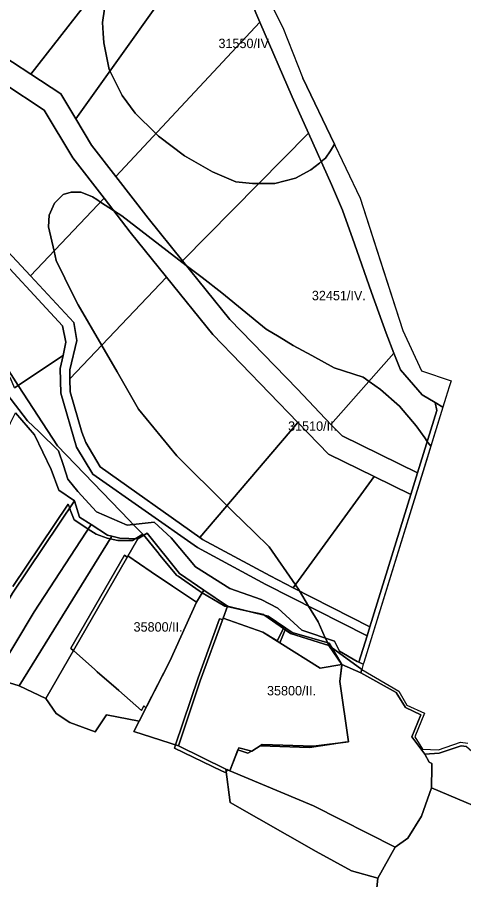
# Model space of a CAD drawing. Extents: x -522079 to -518833, y -1142400 to -1139961.
# Drawn here: x -519685.2 to -519448.3, y -1141371.1 to -1140913.1 of the extents above; entities that cross this region are included whole.
import ezdxf

# ---------------------------------------------------------------- set-up
doc = ezdxf.new("R2010")
doc.units = 0
for name, color, linetype in [('95560013', 7, 'Continuous'), ('95590013', 7, 'Continuous'), ('95610013', 7, 'Continuous'), ('95620013', 7, 'Continuous'), ('95630013', 7, 'Continuous'), ('95640013', 7, 'Continuous'), ('95660013', 7, 'Continuous')]:
    doc.layers.add(name, color=color, linetype=linetype)

msp = doc.modelspace()

# ---------------------------------------------------------------- linework, layer by layer
at = {"layer": '95560013'}
for points in [[(-519758.42, -1140883.91), (-519698.98, -1140816.54), (-519677.02, -1140829.78), (-519655.55, -1140840.89), (-519633.63, -1140850.83), (-519613.39, -1140860.38), (-519678.04, -1140943.34), (-519697.68, -1140930.5)], [(-519654.13, -1140967.02), (-519587.52, -1140873.31), (-519580.34, -1140878), (-519573.15, -1140884.93), (-519566.48, -1140893.71), (-519561.03, -1140904.86), (-519556.41, -1140915.6), (-519632.87, -1140997.67), (-519645.74, -1140981.03)], [(-519530.67, -1140974.63), (-519597.55, -1141042.38), (-519615.79, -1141019.75), (-519632.87, -1140997.67), (-519556.41, -1140915.6), (-519539.28, -1140955.41)], [(-519692.38, -1140948.3), (-519670.91, -1140962.34), (-519655.67, -1140987.81), (-519639.1, -1141009.23), (-519678.16, -1141050.41), (-519704.97, -1141021.67), (-519737.76, -1141001.71), (-519738.84, -1141001.14)], [(-519597.55, -1141042.38), (-519530.67, -1140974.63), (-519518.48, -1141001.84), (-519512.69, -1141015.45), (-519506.32, -1141033.4), (-519497.19, -1141059.15), (-519489.53, -1141080.75), (-519485.33, -1141091.52), (-519518.89, -1141129.28), (-519536.59, -1141110.65), (-519572.39, -1141073.59)], [(-519678.16, -1141050.41), (-519639.1, -1141009.23), (-519625.22, -1141027.17), (-519605.96, -1141051.06), (-519657.23, -1141105.11), (-519657.33, -1141100.32), (-519653.67, -1141084.78), (-519655.12, -1141075.09)], [(-519605.96, -1141051.06), (-519581.39, -1141081.54), (-519536.28, -1141128.25), (-519588.4, -1141189.29), (-519641.2, -1141151.84), (-519648.88, -1141138.93), (-519650.97, -1141133.45), (-519657.08, -1141111.95), (-519657.23, -1141105.11)], [(-519462.56, -1141121.92), (-519472.79, -1141154.97), (-519512.81, -1141135.27), (-519518.89, -1141129.28), (-519485.33, -1141091.52), (-519481.95, -1141100.21), (-519470.4, -1141113.6), (-519463.51, -1141117.64)], [(-519588.4, -1141189.29), (-519536.28, -1141128.25), (-519519.99, -1141145.11), (-519495.79, -1141157.02), (-519538.78, -1141215.99), (-519550.99, -1141209.75), (-519586.93, -1141190.33)], [(-519476.38, -1141166.58), (-519498.1, -1141236.79), (-519538.78, -1141215.99), (-519495.79, -1141157.02)]]:
    msp.add_lwpolyline(points, close=True, dxfattribs=at)
at = {"layer": '95590013'}
msp.add_lwpolyline([(-519702.3, -1141032.7), (-519661.22, -1141076.98), (-519659.49, -1141085.69), (-519660.92, -1141092.62), (-519686.59, -1141109.94), (-519688.8, -1141104.67), (-519698.11, -1141093.5), (-519702.87, -1141087.27), (-519704.67, -1141084.75), (-519705.02, -1141083.87), (-519715.52, -1141069.7), (-519725.48, -1141067.48)], close=True, dxfattribs=at)
at = {"layer": '95610013'}
for points in [[(-519587.52, -1140873.31), (-519654.13, -1140967.02), (-519662.03, -1140953.81), (-519678.04, -1140943.34), (-519613.39, -1140860.38), (-519591.11, -1140871.05)], [(-519555.19, -1141299.24), (-519560.68, -1141302.79), (-519567.64, -1141300.94), (-519572.4, -1141313.2), (-519574.58, -1141312.28), (-519599.57, -1141299.96), (-519588.13, -1141265.46), (-519575.99, -1141232.08), (-519554.92, -1141239.55), (-519545.8, -1141245.26), (-519524.47, -1141258.63), (-519512.96, -1141256.69), (-519514.13, -1141265.79), (-519509.48, -1141297.81), (-519527.97, -1141300.15)]]:
    msp.add_lwpolyline(points, close=True, dxfattribs=at)
at = {"layer": '95620013'}
for points in [[(-519687.67, -1141218.86), (-519709.65, -1141256.63), (-519720.8, -1141249.93), (-519714.2, -1141233.06), (-519705.26, -1141212.3), (-519728.23, -1141211.06), (-519688.75, -1141128.51), (-519686.19, -1141123.12), (-519676.06, -1141134.77), (-519667.13, -1141153.28), (-519663.19, -1141164.28), (-519654.81, -1141169.94)], [(-519697.46, -1141263.95), (-519709.65, -1141256.63), (-519687.67, -1141218.86), (-519654.81, -1141169.94), (-519652.19, -1141178.57), (-519646.01, -1141182.51), (-519676.14, -1141228.74)], [(-519635, -1141188.59), (-519684.2, -1141268.01), (-519697.46, -1141263.95), (-519676.14, -1141228.74), (-519646.01, -1141182.51), (-519637.37, -1141188.02)], [(-519670.06, -1141274.78), (-519621.3, -1141190.09), (-519616.23, -1141186.99), (-519599.05, -1141208.49), (-519586.25, -1141217.21), (-519590.16, -1141223.69), (-519604.3, -1141255.01), (-519620.55, -1141286.87), (-519637.83, -1141283.43), (-519643.91, -1141292.54), (-519657.26, -1141287.51), (-519664.55, -1141282.82)], [(-519684.2, -1141268.01), (-519635, -1141188.59), (-519630.7, -1141189.62), (-519621.3, -1141190.09), (-519670.06, -1141274.78)], [(-519620.55, -1141286.87), (-519604.3, -1141255.01), (-519590.16, -1141223.69), (-519586.25, -1141217.21), (-519573.7, -1141225.77), (-519575.99, -1141232.08), (-519588.13, -1141265.46), (-519599.57, -1141299.96), (-519623.35, -1141292.36)], [(-519554.92, -1141239.55), (-519575.99, -1141232.08), (-519573.7, -1141225.77), (-519552.03, -1141231.12), (-519542.77, -1141237.45), (-519545.8, -1141245.26)], [(-519470.8, -1141337.38), (-519477.91, -1141348.96), (-519484.66, -1141353.81), (-519528.06, -1141331.89), (-519572.4, -1141313.2), (-519567.64, -1141300.94), (-519560.68, -1141302.79), (-519555.19, -1141299.24), (-519527.97, -1141300.15), (-519509.48, -1141297.81), (-519514.13, -1141265.79), (-519512.96, -1141256.69), (-519502.94, -1141261.24), (-519484.08, -1141271.62), (-519479.21, -1141279.64), (-519471.1, -1141283.41), (-519475.87, -1141295.24), (-519468.94, -1141304.33), (-519466.74, -1141308.54), (-519465.25, -1141309.34), (-519465.26, -1141311.18), (-519465.42, -1141322.27)], [(-519385.2, -1141356.16), (-519465.42, -1141322.27), (-519465.26, -1141311.18), (-519465.25, -1141309.34), (-519466.74, -1141308.54), (-519468.94, -1141304.33), (-519461.31, -1141303.85), (-519449.71, -1141299.98), (-519446.9, -1141300.29), (-519442.41, -1141304.27), (-519431.85, -1141306.14), (-519427.38, -1141312.36), (-519420.99, -1141316.12), (-519419.15, -1141315.48), (-519371.28, -1141333.68)], [(-519528.06, -1141331.89), (-519484.66, -1141353.81), (-519493.9, -1141370.24), (-519507.9, -1141366.28), (-519526.67, -1141356.01), (-519572.25, -1141330.06), (-519574.58, -1141312.28), (-519572.4, -1141313.2)], [(-519494.92, -1141380.6), (-519493.9, -1141370.24), (-519484.66, -1141353.81), (-519477.91, -1141348.96), (-519470.8, -1141337.38), (-519465.42, -1141322.27), (-519385.2, -1141356.16), (-519392.16, -1141399.31), (-519386.73, -1141417.35), (-519402.53, -1141416.1), (-519450.75, -1141420.94), (-519466.91, -1141416.21), (-519490.7, -1141404.57), (-519496.45, -1141402.69), (-519489.99, -1141393.96), (-519488.36, -1141388.76)]]:
    msp.add_lwpolyline(points, close=True, dxfattribs=at)
msp.add_lwpolyline([(-519697.46, -1141263.95), (-519684.2, -1141268.01), (-519670.06, -1141274.78), (-519664.55, -1141282.82), (-519657.26, -1141287.51), (-519643.91, -1141292.54), (-519637.83, -1141283.43), (-519620.55, -1141286.87), (-519623.35, -1141292.36), (-519599.57, -1141299.96), (-519574.58, -1141312.28), (-519572.25, -1141330.06), (-519526.67, -1141356.01), (-519507.9, -1141366.28), (-519493.9, -1141370.24), (-519494.92, -1141380.6)], dxfattribs=at)
at = {"layer": '95630013'}
for points in [[(-519690.7, -1141113), (-519679.71, -1141127.39), (-519673.55, -1141133.3), (-519663.4, -1141143.35), (-519660.65, -1141151.03), (-519658.41, -1141158.35), (-519653.03, -1141164.92), (-519643.13, -1141175.65), (-519626.9, -1141182.72), (-519612.48, -1141181.23), (-519603.54, -1141189.56), (-519590.58, -1141204.82), (-519572.33, -1141216.46), (-519555.86, -1141222.18), (-519546.94, -1141226.78), (-519534.2, -1141238.58), (-519516.96, -1141244.4), (-519514.28, -1141249.74), (-519504.82, -1141255.11), (-519503.9, -1141255.56), (-519501.64, -1141256.67), (-519502.46, -1141259.44), (-519502.94, -1141261.24), (-519512.96, -1141256.69), (-519519.64, -1141245.38), (-519539.27, -1141239.84), (-519542.77, -1141237.45), (-519552.03, -1141231.12), (-519573.7, -1141225.77), (-519586.25, -1141217.21), (-519599.05, -1141208.49), (-519616.23, -1141186.99), (-519621.3, -1141190.09), (-519630.7, -1141189.62), (-519635, -1141188.59), (-519637.37, -1141188.02), (-519646.01, -1141182.51), (-519652.19, -1141178.57), (-519654.81, -1141169.94), (-519663.19, -1141164.28), (-519667.13, -1141153.28), (-519676.06, -1141134.77), (-519686.19, -1141123.12)], [(-519446.9, -1141300.29), (-519449.71, -1141299.98), (-519461.31, -1141303.85), (-519468.94, -1141304.33), (-519475.87, -1141295.24), (-519471.1, -1141283.41), (-519479.21, -1141279.64), (-519484.08, -1141271.62), (-519502.94, -1141261.24), (-519502.46, -1141259.44), (-519482.78, -1141270.88), (-519478.58, -1141278.28), (-519469.18, -1141282.65), (-519474.2, -1141295.1), (-519470.14, -1141301.74), (-519461.74, -1141302), (-519449.98, -1141298.09), (-519446.22, -1141298.48)]]:
    msp.add_lwpolyline(points, dxfattribs=at)
msp.add_lwpolyline([(-519462.56, -1141121.92), (-519463.51, -1141117.64), (-519459.37, -1141120.07), (-519501.33, -1141255.67), (-519501.64, -1141256.67), (-519503.9, -1141255.56), (-519499.59, -1141241.58), (-519498.1, -1141236.79), (-519476.38, -1141166.58), (-519472.79, -1141154.97)], close=True, dxfattribs=at)
at = {"layer": '95640013'}
for points in [[(-519569.14, -1140869.38), (-519544.31, -1140918.54), (-519533.66, -1140945.39), (-519503.31, -1141009.21), (-519480.71, -1141079.48), (-519470.66, -1141100.87), (-519455.06, -1141106.14), (-519456.05, -1141109.33), (-519457.77, -1141114.91), (-519459.37, -1141120.07), (-519463.51, -1141117.64), (-519470.4, -1141113.6), (-519481.95, -1141100.21), (-519485.33, -1141091.52), (-519489.53, -1141080.75), (-519497.19, -1141059.15), (-519506.32, -1141033.4), (-519512.69, -1141015.45), (-519518.48, -1141001.84), (-519530.67, -1140974.63), (-519539.28, -1140955.41), (-519556.41, -1140915.6), (-519561.03, -1140904.86)], [(-519697.68, -1140930.5), (-519678.04, -1140943.34), (-519662.03, -1140953.81), (-519654.13, -1140967.02), (-519645.74, -1140981.03), (-519632.87, -1140997.67), (-519615.79, -1141019.75), (-519597.55, -1141042.38), (-519572.39, -1141073.59), (-519536.59, -1141110.65), (-519518.89, -1141129.28), (-519512.81, -1141135.27), (-519472.79, -1141154.97), (-519476.38, -1141166.58), (-519495.79, -1141157.02), (-519519.99, -1141145.11), (-519536.28, -1141128.25), (-519581.39, -1141081.54), (-519605.96, -1141051.06), (-519625.22, -1141027.17), (-519639.1, -1141009.23), (-519655.67, -1140987.81), (-519670.91, -1140962.34), (-519692.38, -1140948.3)], [(-519704.97, -1141021.67), (-519678.16, -1141050.41), (-519655.12, -1141075.09), (-519653.67, -1141084.78), (-519657.33, -1141100.32), (-519657.23, -1141105.11), (-519657.08, -1141111.95), (-519650.97, -1141133.45), (-519648.88, -1141138.93), (-519641.2, -1141151.84), (-519588.4, -1141189.29), (-519586.93, -1141190.33), (-519550.99, -1141209.75), (-519538.78, -1141215.99), (-519498.1, -1141236.79), (-519499.59, -1141241.58), (-519553.27, -1141214.2), (-519589.6, -1141194.6), (-519645.14, -1141155.67), (-519653.82, -1141141.35), (-519662.06, -1141112.71), (-519662.35, -1141099.54), (-519660.92, -1141092.62), (-519659.49, -1141085.69), (-519661.22, -1141076.98), (-519702.3, -1141032.7)], [(-519686.59, -1141109.94), (-519660.92, -1141092.62), (-519662.35, -1141099.54), (-519662.06, -1141112.71), (-519653.82, -1141141.35), (-519645.14, -1141155.67), (-519589.6, -1141194.6), (-519553.27, -1141214.2), (-519499.59, -1141241.58), (-519503.9, -1141255.56), (-519504.82, -1141255.11), (-519514.28, -1141249.74), (-519516.96, -1141244.4), (-519534.2, -1141238.58), (-519546.94, -1141226.78), (-519555.86, -1141222.18), (-519572.33, -1141216.46), (-519590.58, -1141204.82), (-519603.54, -1141189.56), (-519612.48, -1141181.23), (-519626.9, -1141182.72), (-519643.13, -1141175.65), (-519653.03, -1141164.92), (-519658.41, -1141158.35), (-519660.65, -1141151.03), (-519663.4, -1141143.35), (-519673.55, -1141133.3), (-519679.71, -1141127.39), (-519690.7, -1141113)]]:
    msp.add_lwpolyline(points, dxfattribs=at)
msp.add_lwpolyline([(-519524.47, -1141258.63), (-519545.8, -1141245.26), (-519542.77, -1141237.45), (-519539.27, -1141239.84), (-519519.64, -1141245.38), (-519512.96, -1141256.69)], close=True, dxfattribs=at)
at = {"layer": '95660013'}
for points in [[(-519569.14, -1140869.38), (-519544.31, -1140918.54), (-519533.66, -1140945.39), (-519516.96, -1140980.51), (-519518.95, -1140984.06), (-519521.57, -1140987.86), (-519523.9, -1140989.74), (-519524.88, -1140990.52), (-519529.4, -1140994.15), (-519537.54, -1140998.54), (-519548.5, -1141001.37), (-519557.07, -1141001.37), (-519560.4, -1141001.37), (-519569.16, -1141000.43), (-519581.69, -1140995.09), (-519596.41, -1140986.61), (-519610.19, -1140976.25), (-519611.61, -1140974.85), (-519622.71, -1140964), (-519629.6, -1140954.57), (-519636.06, -1140941.6), (-519636.49, -1140940.75), (-519639.31, -1140926.61), (-519639.6, -1140921.53), (-519639.93, -1140915.93), (-519638.05, -1140902.43)], [(-519638.05, -1140902.43), (-519639.93, -1140915.93), (-519639.6, -1140921.53), (-519639.31, -1140926.61), (-519636.49, -1140940.75), (-519636.06, -1140941.6), (-519629.6, -1140954.57), (-519622.71, -1140964), (-519611.61, -1140974.85), (-519610.19, -1140976.25), (-519596.41, -1140986.61), (-519581.69, -1140995.09), (-519569.16, -1141000.43), (-519560.4, -1141001.37), (-519557.07, -1141001.37), (-519548.5, -1141001.37), (-519537.54, -1140998.54), (-519529.4, -1140994.15), (-519524.88, -1140990.52), (-519523.9, -1140989.74), (-519521.57, -1140987.86), (-519518.95, -1140984.06), (-519516.96, -1140980.51), (-519533.66, -1140945.39), (-519503.31, -1141009.21), (-519492.53, -1141042.73), (-519480.71, -1141079.48), (-519470.66, -1141100.87), (-519455.06, -1141106.14), (-519456.05, -1141109.33), (-519457.77, -1141114.91), (-519459.37, -1141120.07), (-519465.79, -1141140.81), (-519467.15, -1141139), (-519467.63, -1141138.31), (-519468.94, -1141136.48), (-519473.54, -1141130.01), (-519482.42, -1141119.57), (-519492.53, -1141110.66), (-519498.57, -1141106.42), (-519501.71, -1141104.21), (-519517.02, -1141099.29), (-519528.96, -1141092.71), (-519538.76, -1141087.32), (-519546.31, -1141082.8), (-519553.15, -1141078.71), (-519576.72, -1141059.36), (-519587.13, -1141051.34), (-519595.58, -1141044.83), (-519629.69, -1141018.52), (-519634.16, -1141015.62), (-519640.97, -1141011.2), (-519643.01, -1141009.87), (-519645.3, -1141008.38), (-519649.09, -1141006.86), (-519651.43, -1141005.93), (-519656.63, -1141005.93), (-519660.92, -1141007.16), (-519665.51, -1141011.76), (-519668.27, -1141018.21), (-519668.57, -1141024.35), (-519665.69, -1141037.26), (-519664.59, -1141042.17), (-519655.31, -1141061.04), (-519652.96, -1141065.82), (-519640.38, -1141087.34), (-519632.14, -1141101.44), (-519620.81, -1141121.1), (-519600.6, -1141145.98), (-519573.98, -1141172.41), (-519570.9, -1141175.46), (-519559.55, -1141186.49), (-519551.62, -1141194.2), (-519537.64, -1141214.42), (-519535.7, -1141217.23), (-519535.41, -1141217.71), (-519530.59, -1141225.77), (-519525.59, -1141234.12), (-519521.78, -1141242.52), (-519521.65, -1141242.82), (-519520.61, -1141245.1), (-519520.44, -1141245.48), (-519519.93, -1141246.59), (-519540.28, -1141240.34), (-519543.11, -1141238.33), (-519543.97, -1141237.72), (-519553.9, -1141230.66), (-519554.03, -1141230.56), (-519554.4, -1141230.29), (-519563.68, -1141228.24), (-519573.78, -1141226), (-519575.01, -1141225.73), (-519587.11, -1141218.63), (-519588.75, -1141217.67), (-519599.88, -1141209.94), (-519600.53, -1141209.49), (-519609.5, -1141198.7), (-519609.98, -1141198.13), (-519610.5, -1141197.51), (-519618.13, -1141188.15), (-519618.57, -1141187.61), (-519623.62, -1141182.38), (-519625.86, -1141180.06), (-519663.82, -1141140.73), (-519684.63, -1141108.61), (-519698.14, -1141087.76)], [(-519698.14, -1141087.76), (-519684.63, -1141108.61), (-519663.82, -1141140.73), (-519625.86, -1141180.06), (-519623.62, -1141182.38), (-519618.57, -1141187.61), (-519622.57, -1141190.02), (-519623.97, -1141190.87), (-519631.88, -1141190.86), (-519635.9, -1141190.04), (-519637.58, -1141189.69), (-519643.39, -1141187.64), (-519647.55, -1141184.87), (-519648.76, -1141184.06), (-519654.98, -1141179.93), (-519657.04, -1141174.68), (-519657.39, -1141173.78), (-519658.25, -1141171.6), (-519687.52, -1141215.32)], [(-519687.52, -1141215.32), (-519658.25, -1141171.6), (-519657.39, -1141173.78), (-519657.04, -1141174.68), (-519654.98, -1141179.93), (-519648.76, -1141184.06), (-519647.55, -1141184.87), (-519643.39, -1141187.64), (-519637.58, -1141189.69), (-519635.9, -1141190.04), (-519631.88, -1141190.86), (-519623.97, -1141190.87), (-519622.57, -1141190.02), (-519618.57, -1141187.61), (-519618.13, -1141188.15), (-519610.5, -1141197.51), (-519609.98, -1141198.13), (-519609.5, -1141198.7), (-519600.53, -1141209.49), (-519599.88, -1141209.94), (-519588.75, -1141217.67), (-519587.11, -1141218.63), (-519575.01, -1141225.73), (-519573.78, -1141226), (-519563.68, -1141228.24), (-519554.4, -1141230.29), (-519554.03, -1141230.56), (-519553.9, -1141230.66), (-519543.97, -1141237.72), (-519547.36, -1141244.28), (-519554.92, -1141239.55), (-519575.99, -1141232.08), (-519576.31, -1141232.95), (-519577.81, -1141232.43), (-519589.22, -1141263.89), (-519601.17, -1141299.45), (-519601.76, -1141301.21), (-519576.76, -1141313.26), (-519574.4, -1141314.26), (-519574.34, -1141314.1), (-519573.79, -1141312.61), (-519572.4, -1141313.2), (-519568.11, -1141302.15), (-519562.8, -1141303.9), (-519560.96, -1141302.71), (-519560.68, -1141302.79), (-519556.3, -1141299.95), (-519530.07, -1141300.79), (-519511.43, -1141298.06), (-519511.23, -1141298.03), (-519509.48, -1141297.81), (-519514.13, -1141265.79), (-519513.04, -1141257.34), (-519512.96, -1141256.69), (-519519.93, -1141246.59), (-519503.16, -1141258.92), (-519502.46, -1141259.44), (-519482.78, -1141270.88), (-519478.58, -1141278.28), (-519469.18, -1141282.65), (-519474.2, -1141295.1), (-519470.14, -1141301.74), (-519461.74, -1141302), (-519449.98, -1141298.09), (-519446.22, -1141298.48)]]:
    msp.add_lwpolyline(points, dxfattribs=at)
for points in [[(-519501.33, -1141255.67), (-519501.64, -1141256.67), (-519502.46, -1141259.44), (-519503.16, -1141258.92), (-519519.93, -1141246.59), (-519520.44, -1141245.48), (-519520.61, -1141245.1), (-519521.65, -1141242.82), (-519521.78, -1141242.52), (-519525.59, -1141234.12), (-519530.59, -1141225.77), (-519535.41, -1141217.71), (-519535.7, -1141217.23), (-519537.64, -1141214.42), (-519551.62, -1141194.2), (-519559.55, -1141186.49), (-519570.9, -1141175.46), (-519573.98, -1141172.41), (-519600.6, -1141145.98), (-519620.81, -1141121.1), (-519632.14, -1141101.44), (-519640.38, -1141087.34), (-519652.96, -1141065.82), (-519655.31, -1141061.04), (-519664.59, -1141042.17), (-519665.69, -1141037.26), (-519668.57, -1141024.35), (-519668.27, -1141018.21), (-519665.51, -1141011.76), (-519660.92, -1141007.16), (-519656.63, -1141005.93), (-519651.43, -1141005.93), (-519649.09, -1141006.86), (-519645.3, -1141008.38), (-519643.01, -1141009.87), (-519640.97, -1141011.2), (-519634.16, -1141015.62), (-519629.69, -1141018.52), (-519595.58, -1141044.83), (-519587.13, -1141051.34), (-519576.72, -1141059.36), (-519553.15, -1141078.71), (-519546.31, -1141082.8), (-519538.76, -1141087.32), (-519528.96, -1141092.71), (-519517.02, -1141099.29), (-519501.71, -1141104.21), (-519498.57, -1141106.42), (-519492.53, -1141110.66), (-519482.42, -1141119.57), (-519473.54, -1141130.01), (-519468.94, -1141136.48), (-519467.63, -1141138.31), (-519467.15, -1141139), (-519465.79, -1141140.81), (-519468.33, -1141149.01)], [(-519628.29, -1141198.7), (-519626.84, -1141199.71), (-519626.51, -1141199.14), (-519614.16, -1141207.48), (-519602.83, -1141215.13), (-519590.16, -1141223.69), (-519604.3, -1141255.01), (-519616.91, -1141279.74), (-519618.04, -1141278.78), (-519619.23, -1141281.17), (-519631.3, -1141270.6), (-519632.69, -1141269.38), (-519642.73, -1141260.59), (-519644.11, -1141259.38), (-519655.44, -1141249.39), (-519656.54, -1141248.43), (-519656.82, -1141248.18)], [(-519628.29, -1141198.7), (-519656.82, -1141248.18), (-519656.54, -1141248.43), (-519655.44, -1141249.39), (-519644.11, -1141259.38), (-519642.73, -1141260.59), (-519632.69, -1141269.38), (-519631.3, -1141270.6), (-519619.23, -1141281.17), (-519618.04, -1141278.78), (-519616.91, -1141279.74), (-519604.3, -1141255.01), (-519590.16, -1141223.69), (-519602.83, -1141215.13), (-519614.16, -1141207.48), (-519626.51, -1141199.14), (-519626.84, -1141199.71)], [(-519543.97, -1141237.72), (-519543.11, -1141238.33), (-519540.28, -1141240.34), (-519519.93, -1141246.59), (-519512.96, -1141256.69), (-519513.04, -1141257.34), (-519514.13, -1141265.79), (-519509.48, -1141297.81), (-519511.23, -1141298.03), (-519511.43, -1141298.06), (-519530.07, -1141300.79), (-519556.3, -1141299.95), (-519560.68, -1141302.79), (-519560.96, -1141302.71), (-519562.8, -1141303.9), (-519568.11, -1141302.15), (-519572.4, -1141313.2), (-519573.79, -1141312.61), (-519574.34, -1141314.1), (-519574.4, -1141314.26), (-519576.76, -1141313.26), (-519601.76, -1141301.21), (-519601.17, -1141299.45), (-519589.22, -1141263.89), (-519577.81, -1141232.43), (-519576.31, -1141232.95), (-519575.99, -1141232.08), (-519554.92, -1141239.55), (-519547.36, -1141244.28)]]:
    msp.add_lwpolyline(points, close=True, dxfattribs=at)

# ---------------------------------------------------------------- texts
for s, rotation, p in [('31550/IV.', 360, (-519578.45, -1140929.45)), ('32451/IV.', 0, (-519528.88, -1141063.35)), ('31510/II.', 0, (-519541.52, -1141132.68)), ('35800/II.', 0, (-519623.49, -1141239.31)), ('35800/II.', 0, (-519552.7, -1141273.17))]:
    msp.add_text(s, height=5, rotation=rotation, dxfattribs=at).set_placement(p)

doc.saveas('drawing.dxf')
